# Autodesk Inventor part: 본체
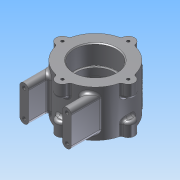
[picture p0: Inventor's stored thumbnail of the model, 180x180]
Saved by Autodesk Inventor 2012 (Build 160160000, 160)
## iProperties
Created: 2015-03
Part Number: 본체
Material: Default
Document SubType Name: Modeling
Designer: net
Density: 1 g/cm^3
Author: net
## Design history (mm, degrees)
sketch "스케치1"
  geometry: C1 r 37 at (0, 0); 1 further point
  constraints: 1 centre point, 1 coincident
  dimensions: "d0" = 74 diameter of C1
extrude "돌출1" new body sketch "스케치1" distance "d1" = 52; taper "d2" = 0 deg
hole "구멍1" diameter "d5" = 42; stored, may be unused: countersink angle "d9" = 90 deg, drill point angle "d11" = 0 deg; dims "d3" = 10, "d4" = 10, "d6" = 6, "d7" = 47, "d8" = 22, "d10" = 30
hole "구멍2" diameter "d14" = 47; stored, may be unused: countersink angle "d18" = 90 deg, drill point angle "d20" = 0 deg; dims "d12" = 10, "d13" = 10, "d15" = 6, "d16" = 47, "d17" = 22, "d19" = 22
sketch "스케치2"
  geometry: C1 r 23.5 at (0, 0) reference; C2 r 7 at (0, 37); 1 further point
  constraints: 1 centre point, 1 coincident, 1 vertical alignment
  dimensions: "d21" = 37 distance of point (0, 37) C1.centre; "d22" = 14 diameter of C2
extrude "돌출2" join sketch "스케치2" distance "d23" = 15; taper "d24" = 0 deg
hole "구멍3" diameter "d27" = 3.242; stored, may be unused: countersink angle "d31" = 90 deg, drill point angle "d33" = 118 deg; dims "d25" = 10, "d26" = 10, "d28" = 8, "d29" = 47, "d30" = 22, "d32" = 11
node "작업 평면1"
node "작업 평면2"
extrude "돌출3" join sketch "스케치4" stored distance "d41" = 15; taper "d42" = 0 deg
node "작업 평면3"
hole "구멍4" diameter "d46" = 4.134; stored, may be unused: countersink angle "d50" = 90 deg, drill point angle "d52" = 118 deg; dims "d44" = 10, "d45" = 10, "d47" = 6, "d48" = 47, "d49" = 22, "d51" = 8
hole "구멍5" diameter "d55" = 4.134; stored, may be unused: countersink angle "d59" = 90 deg, drill point angle "d61" = 118 deg; dims "d53" = 10, "d54" = 10, "d56" = 6, "d57" = 47, "d58" = 22, "d60" = 8
fillet "모깎기1" dims "d62" = 0.3
chamfer "모따기1" distance "d63" = 1; stored, may be unused: second distance "d64" = 2, angle "d65" = 45 deg
fillet "모깎기2" dims "d66" = 3
fillet "모깎기3" dims "d67" = 3
fillet "모깎기4" dims "d68" = 3
fillet "모깎기5" dims "d69" = 3
fillet "모깎기6" dims "d70" = 3
fillet "모깎기7" dims "d71" = 3
sketch "스케치5"
  geometry: L1 (29, -24)-(29, -56) reference; L2 (29, -56)-(19, -56) reference; L3 (19, -56)-(19, -36.661) reference; L4 (-19, -36.661)-(-19, -56) reference; L5 (-19, -56)-(-29, -56) reference; L6 (-29, -56)-(-29, -24) reference; L7 (0, 0)-(-26.163, 26.163); L8 (0, 0)-(-51.08, 0); C1 r 21 at (0, 0) reference; A1 r 37 centre (0, 0) between (29.6, -22.2) and (-29.6, -22.2) reference; A2 r 3 centre (32, -24) between (29.6, -22.2) and (29, -24) reference; A3 r 3 centre (16, -36.661) between (19, -36.661) and (14.8, -33.911) reference; A4 r 37 centre (0, 0) between (-14.8, -33.911) and (14.8, -33.911) reference; A5 r 3 centre (-16, -36.661) between (-14.8, -33.911) and (-19, -36.661) reference; A6 r 3 centre (-32, -24) between (-29, -24) and (-29.6, -22.2) reference; 1 further point
  constraints: 4 end point, 1 perpendicular, 1 point on circle
  dimensions: "d72" = 45 deg angle of L8 L7
  node "절단 모서리 투영2"
node "작업 평면4"
sketch "스케치6"
  geometry: L1 (23.5, -25)-(-23.5, -25) reference; L2 (-18.921, 26)-(18.921, 26) reference; 3 further points
  constraints: 1 coincident, 1 other
  dimensions: "d73" = 26 distance from line of L2 point (0, 0)
feature "엠보싱1" sketch "스케치6" dims "d1" = 52, "d74" = 0.5, "d75" = 0
sketch "스케치7"
  geometry: 1 further point
node "솔리드1"
pattern_circular "원형 패턴1" dims angle "d35" = 360 deg
mirror "대칭1"
mirror "대칭2"
mirror "대칭3"
other parameters: "d37" = -56, "d40" = 24, "d43" = 0
